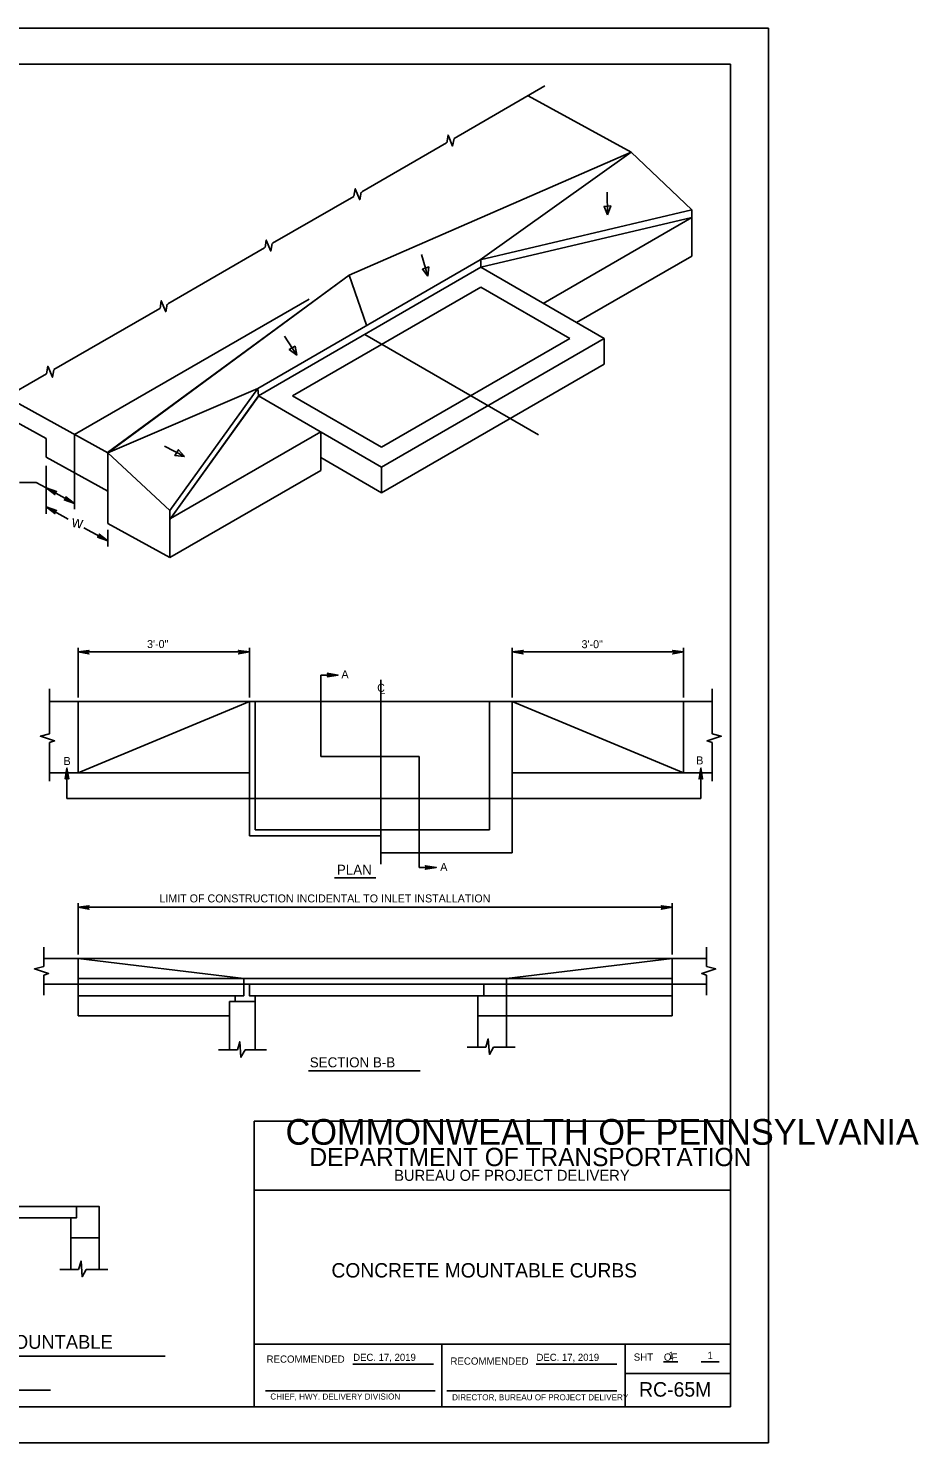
# Model space of a CAD drawing. Extents: x 638443 to 639347, y 298415 to 299009.
# Drawn here: x 638973 to 639347, y 298415 to 299009 of the extents above; entities that cross this region are included whole.
import ezdxf

# ---------------------------------------------------------------- set-up
doc = ezdxf.new("R2010")
doc.units = 0
for name, color, linetype in [('1', 7, 'Continuous'), ('2', 7, 'Continuous'), ('3', 7, 'Continuous'), ('PLT-BNDY', 7, 'Continuous')]:
    doc.layers.add(name, color=color, linetype=linetype)

msp = doc.modelspace()

# ---------------------------------------------------------------- linework, layer by layer
at = {"layer": '1'}
for p, q in [((639268.08, 298993.73), (638482.08, 298993.73)), ((639268.08, 298429.73), (639268.08, 298993.73)), ((639216.38, 298939.93), (639216.47, 298930.45)), ((639138.4, 298913.68), (639141.04, 298904.58)), ((639115.26, 298884.06), (639108.01, 298905.02)), ((639115.26, 298884.06), (639108.01, 298905.02)), ((639080.79, 298879.39), (639086.04, 298871.51)), ((639030.34, 298833.22), (639038.74, 298828.85)), ((639268.08, 298549.73), (639068.08, 298549.73)), ((639068.08, 298549.73), (639068.08, 298429.73)), ((639268.08, 298520.76), (639268.08, 298549.73)), ((639068.08, 298456.09), (639068.08, 298520.76)), ((639068.08, 298520.76), (639268.08, 298520.76)), ((639268.08, 298456.09), (639068.08, 298456.09)), ((639146.88, 298429.73), (639146.88, 298456.09)), ((639146.88, 298456.09), (639146.88, 298429.73)), ((639223.88, 298429.73), (639223.88, 298456.09)), ((639223.88, 298456.09), (639223.88, 298443.77)), ((639268.08, 298429.73), (639268.08, 298456.09)), ((639109.55, 298447.72), (639143.43, 298447.72)), ((639186.54, 298447.72), (639220.41, 298447.72)), ((639223.88, 298443.77), (639268.08, 298443.77)), ((639239.95, 298448.7), (639246.09, 298448.7)), ((639255.76, 298448.7), (639263.4, 298448.7)), ((639072.84, 298436.49), (639144.09, 298436.49)), ((639149.01, 298436.49), (639220.35, 298436.49)), ((638482.08, 298429.73), (639268.08, 298429.73)), ((639068.08, 298429.73), (639146.88, 298429.73)), ((639146.88, 298429.73), (639223.88, 298429.73))]:
    msp.add_line(p, q, dxfattribs=at)
for points in [[(639149, 298960.68), (639149.51, 298963.89), (639151.42, 298959.24), (639152.03, 298962.43)], [(639109.99, 298938.16), (639110.5, 298941.37), (639112.41, 298936.72), (639113.02, 298939.91)], [(639072.64, 298916.6), (639073.15, 298919.8), (639075.06, 298915.15), (639075.67, 298918.35)], [(639028.51, 298891.12), (639029.02, 298894.32), (639030.94, 298889.68), (639031.54, 298892.87)], [(638980.87, 298863.61), (638981.38, 298866.81), (638983.29, 298862.17), (638983.89, 298865.36)]]:
    msp.add_lwpolyline(points, dxfattribs=at)
for points in [[(639006.62, 298830.49), (639108.01, 298905.02), (639226.35, 298956.64), (639163, 298911.47), (639069.55, 298857.52)], [(639226.35, 298956.64), (639251.9, 298932.45), (639163, 298911.47)], [(639032.63, 298802.4), (639032.63, 298806.16), (639069.55, 298857.52), (639163, 298911.47), (639251.9, 298932.45), (639251.9, 298929.25), (639163.27, 298908.34), (639069.82, 298854.38)], [(639216.47, 298930.45), (639217.85, 298934.18), (639215.02, 298933.94)], [(639141.04, 298904.58), (639141.36, 298908.54), (639138.71, 298907.55)], [(639086.04, 298871.51), (639082.81, 298873.81), (639085.28, 298875.2)], [(639006.65, 298830.46), (639069.55, 298857.52), (639032.63, 298806.16)], [(639038.74, 298828.85), (639034.8, 298829.31), (639036.29, 298831.72)]]:
    msp.add_lwpolyline(points, close=True, dxfattribs=at)
at = {"layer": '2'}
for p, q in [((639190.22, 298984.5), (639152.07, 298962.47)), ((639183.15, 298980.42), (639226.35, 298956.65)), ((639148.86, 298960.62), (639113.28, 298940.08)), ((639226.35, 298956.64), (639108.01, 298905.02)), ((639163, 298911.47), (639226.35, 298956.64)), ((639251.9, 298932.45), (639226.35, 298956.64)), ((639109.92, 298938.14), (639075.78, 298918.43)), ((639251.9, 298932.45), (639163, 298911.47)), ((639251.9, 298929.25), (639251.9, 298932.45)), ((639251.9, 298929.25), (639163.27, 298908.34)), ((639189.48, 298893.21), (639251.9, 298929.25)), ((639251.9, 298913.08), (639251.9, 298929.25)), ((639072.46, 298916.51), (639031.76, 298893.01)), ((639203.48, 298885.12), (639251.9, 298913.08)), ((639163, 298911.47), (639069.55, 298857.52)), ((639163.27, 298908.34), (639069.82, 298854.38)), ((639163.27, 298908.34), (639163.27, 298911.55)), ((639215.06, 298878.44), (639163.27, 298908.34)), ((639108.01, 298905.02), (639006.52, 298830.58)), ((639091.17, 298895.04), (638992.65, 298838.16)), ((639163.27, 298900.03), (639084.22, 298854.38)), ((639200.66, 298878.44), (639163.27, 298900.03)), ((639028.46, 298891.11), (638983.92, 298865.39)), ((639187.47, 298838.05), (639114.5, 298880.18)), ((639121.6, 298832.8), (639200.66, 298878.44)), ((639121.6, 298824.48), (639215.06, 298878.44)), ((639215.06, 298867.65), (639215.06, 298878.44)), ((639121.6, 298813.69), (639215.06, 298867.65)), ((638980.79, 298863.58), (638959.89, 298851.51)), ((638964.03, 298853.9), (639006.65, 298830.46)), ((639069.55, 298857.52), (639006.62, 298830.49)), ((639032.63, 298806.16), (639069.55, 298857.52)), ((639032.63, 298802.4), (639069.95, 298854.31)), ((639069.82, 298854.38), (639069.64, 298857.5)), ((639121.6, 298824.48), (639069.82, 298854.38)), ((639121.6, 298832.8), (639084.22, 298854.38)), ((638964.1, 298845.54), (638980.67, 298836.43)), ((638980.67, 298836.43), (638980.67, 298828.6)), ((638992.65, 298806.78), (638992.65, 298838.16)), ((639032.94, 298802.84), (639096.02, 298839.25)), ((639096.02, 298823.08), (639096.02, 298839.25)), ((639006.65, 298830.46), (639006.65, 298800.77)), ((639032.63, 298806.16), (639006.65, 298830.46)), ((638980.67, 298828.6), (639006.65, 298814.31)), ((638980.67, 298804.82), (638980.67, 298824.94)), ((639121.6, 298813.69), (639096.02, 298828.46)), ((639121.6, 298813.69), (639121.6, 298824.48)), ((638976.45, 298818.03), (638969.52, 298818.03)), ((638976.45, 298818.03), (638980.67, 298815.71)), ((639032.63, 298786.48), (639096.02, 298823.08)), ((638980.67, 298815.71), (638992.65, 298809.12)), ((638980.67, 298807.75), (638989.99, 298802.62)), ((639032.63, 298802.4), (639032.63, 298806.16)), ((639006.65, 298800.77), (639032.62, 298786.48)), ((639032.63, 298786.48), (639032.63, 298802.4)), ((638996.56, 298799), (639006.65, 298793.46)), ((639006.65, 298791.12), (639006.65, 298798.16)), ((638994.07, 298727.74), (638994.07, 298748.53)), ((639039.51, 298746.85), (638994.07, 298746.85)), ((639066.07, 298746.85), (639039.51, 298746.85)), ((639066.07, 298727.74), (639066.07, 298748.53)), ((639176.47, 298727.74), (639176.47, 298748.53)), ((639221.91, 298746.85), (639176.47, 298746.85)), ((639248.47, 298746.85), (639221.91, 298746.85)), ((639248.47, 298727.74), (639248.47, 298748.53)), ((639096.13, 298737.1), (639096.13, 298702.94)), ((639096.13, 298737.1), (639103.33, 298737.1)), ((639121.27, 298657.7), (639121.27, 298735.08)), ((638982.07, 298731.29), (638982.07, 298712.37)), ((639260.47, 298731.29), (639260.47, 298712.37)), ((638994.07, 298726.06), (638982.07, 298726.06)), ((638994.07, 298696.06), (639066.07, 298726.06)), ((639066.07, 298726.06), (639176.47, 298726.06)), ((639066.07, 298726.06), (639066.07, 298669.66)), ((639068.47, 298726.06), (639068.47, 298672.06)), ((639166.87, 298726.06), (639166.87, 298672.06)), ((639248.47, 298696.06), (639176.47, 298726.06)), ((639176.47, 298726.06), (639176.47, 298662.46)), ((639248.47, 298726.06), (639260.47, 298726.06)), ((638982.07, 298708.82), (638982.07, 298692.59)), ((639260.47, 298708.82), (639260.47, 298692.59)), ((639096.13, 298702.94), (639137.36, 298702.94)), ((639137.36, 298702.94), (639137.36, 298656.32)), ((638994.07, 298696.06), (638982.07, 298696.06)), ((638989.41, 298685.26), (638989.41, 298698.04)), ((639248.47, 298696.06), (639260.47, 298696.06)), ((639255.71, 298685.26), (639255.71, 298698.04)), ((638989.41, 298685.26), (639255.71, 298685.26)), ((639066.07, 298669.66), (639121.27, 298669.66)), ((639068.47, 298672.06), (639121.27, 298672.06)), ((639166.87, 298672.06), (639121.27, 298672.06)), ((639176.47, 298662.46), (639121.27, 298662.46)), ((639137.36, 298656.32), (639144.56, 298656.32)), ((638994.07, 298619.74), (638994.07, 298641.31)), ((639129.98, 298639.63), (638994.07, 298639.63)), ((639243.67, 298639.63), (639129.98, 298639.63)), ((639243.67, 298619.74), (639243.67, 298641.31)), ((638979.67, 298622.79), (638979.67, 298614.67)), ((639258.07, 298622.79), (639258.07, 298614.67)), ((638979.67, 298618.06), (639258.07, 298618.06)), ((638981.35, 298618.06), (639089.1, 298618.06)), ((638994.07, 298594.06), (638994.07, 298618.06)), ((638994.07, 298618.06), (639063.67, 298609.66)), ((639243.67, 298618.06), (639174.07, 298609.66)), ((639243.67, 298594.06), (639243.67, 298618.06)), ((638979.67, 298611.13), (638979.67, 298602.63)), ((639258.07, 298611.13), (639258.07, 298602.63)), ((639063.67, 298607.26), (638979.67, 298607.26)), ((639063.67, 298609.66), (638994.07, 298609.66)), ((639063.67, 298609.66), (639063.67, 298607.26)), ((639174.07, 298609.66), (639063.67, 298609.66)), ((639066.07, 298607.26), (639063.67, 298607.26)), ((639063.67, 298607.26), (639063.67, 298602.46)), ((639174.07, 298609.66), (639243.67, 298609.66)), ((639174.07, 298609.66), (639174.07, 298607.26)), ((639174.07, 298607.26), (639258.07, 298607.26)), ((639060.07, 298602.46), (638994.07, 298602.46)), ((639057.67, 298600.06), (639068.47, 298600.06)), ((639057.67, 298600.06), (639057.67, 298579.66)), ((639063.67, 298602.46), (639060.07, 298602.46)), ((639060.07, 298602.46), (639060.07, 298600.06)), ((639067.75, 298602.46), (639089.1, 298602.46)), ((639068.47, 298600.06), (639068.47, 298602.46)), ((639068.47, 298602.46), (639068.47, 298579.66)), ((639164.47, 298602.46), (639243.67, 298602.46)), ((639057.67, 298594.06), (638994.07, 298594.06)), ((639174.07, 298594.06), (639243.67, 298594.06)), ((639057.67, 298579.66), (639057.67, 298579.79))]:
    msp.add_line(p, q, dxfattribs=at)
for points in [[(638984.76, 298814.09), (638984.46, 298813.9), (638980.67, 298815.71), (638984.76, 298814.09), (638985.04, 298814.15), (638980.67, 298815.71), (638984.25, 298813.51), (638984.23, 298813.16), (638980.67, 298815.71), (638984.34, 298812.87), (638984.23, 298813.16)], [(638988.58, 298810.75), (638988.87, 298810.95), (638992.65, 298809.12), (638988.58, 298810.75), (638988.29, 298810.69), (638992.65, 298809.12), (638989.09, 298811.33), (638989.11, 298811.68), (638992.65, 298809.12), (638989, 298811.98), (638989.11, 298811.68)], [(638984.76, 298806.13), (638984.46, 298805.93), (638980.67, 298807.75), (638984.76, 298806.13), (638985.04, 298806.19), (638980.67, 298807.75), (638984.25, 298805.55), (638984.23, 298805.2), (638980.67, 298807.75), (638984.34, 298804.9), (638984.23, 298805.2)], [(639002.57, 298795.09), (639002.86, 298795.29), (639006.65, 298793.46), (639002.57, 298795.09), (639002.28, 298795.03), (639006.65, 298793.46), (639003.08, 298795.67), (639003.1, 298796.02), (639006.65, 298793.46), (639002.99, 298796.32), (639003.1, 298796.02)], [(638998.41, 298746.19), (638998.26, 298746.51), (638994.07, 298746.85), (638998.41, 298746.19), (638998.63, 298746), (638994.07, 298746.85), (638998.27, 298746.95), (638998.43, 298747.26), (638994.07, 298746.85), (638998.67, 298747.46), (638998.43, 298747.26)], [(639061.72, 298746.19), (639061.88, 298746.51), (639066.07, 298746.85), (639061.72, 298746.19), (639061.51, 298746), (639066.07, 298746.85), (639061.87, 298746.95), (639061.71, 298747.26), (639066.07, 298746.85), (639061.47, 298747.46), (639061.71, 298747.26)], [(639180.81, 298746.19), (639180.66, 298746.51), (639176.47, 298746.85), (639180.81, 298746.19), (639181.03, 298746), (639176.47, 298746.85), (639180.67, 298746.95), (639180.83, 298747.26), (639176.47, 298746.85), (639181.07, 298747.46), (639180.83, 298747.26)], [(639244.12, 298746.19), (639244.28, 298746.51), (639248.47, 298746.85), (639244.12, 298746.19), (639243.91, 298746), (639248.47, 298746.85), (639244.27, 298746.95), (639244.11, 298747.26), (639248.47, 298746.85), (639243.87, 298747.46), (639244.11, 298747.26)], [(639098.97, 298737.65), (639099.14, 298737.33), (639103.33, 298737.1), (639098.97, 298737.65), (639098.75, 298737.84), (639103.33, 298737.1), (639099.14, 298736.9), (639098.99, 298736.58), (639103.33, 298737.1), (639098.75, 298736.38), (639098.99, 298736.58)], [(638982.07, 298712.37), (638978.3, 298711.42), (638984.2, 298709.46), (638982.07, 298708.82)], [(639260.47, 298712.37), (639264.24, 298711.42), (639258.34, 298709.46), (639260.47, 298708.82)], [(638988.87, 298693.69), (638989.18, 298693.85), (638989.41, 298698.04), (638988.87, 298693.69), (638988.68, 298693.46), (638989.41, 298698.04), (638989.62, 298693.85), (638989.93, 298693.7), (638989.41, 298698.04), (638990.14, 298693.46), (638989.93, 298693.7)], [(639255.16, 298693.69), (639255.48, 298693.85), (639255.71, 298698.04), (639255.16, 298693.69), (639254.97, 298693.46), (639255.71, 298698.04), (639255.91, 298693.85), (639256.23, 298693.7), (639255.71, 298698.04), (639256.44, 298693.46), (639256.23, 298693.7)], [(639140.2, 298656.86), (639140.36, 298656.55), (639144.56, 298656.32), (639140.2, 298656.86), (639139.98, 298657.06), (639144.56, 298656.32), (639140.37, 298656.11), (639140.21, 298655.8), (639144.56, 298656.32), (639139.98, 298655.59), (639140.21, 298655.8)], [(638998.41, 298638.97), (638998.26, 298639.29), (638994.07, 298639.63), (638998.41, 298638.97), (638998.63, 298638.77), (638994.07, 298639.63), (638998.27, 298639.73), (638998.43, 298640.04), (638994.07, 298639.63), (638998.67, 298640.24), (638998.43, 298640.04)], [(639239.32, 298638.97), (639239.48, 298639.29), (639243.67, 298639.63), (639239.32, 298638.97), (639239.11, 298638.77), (639243.67, 298639.63), (639239.47, 298639.73), (639239.31, 298640.04), (639243.67, 298639.63), (639239.07, 298640.24), (639239.31, 298640.04)], [(638979.67, 298614.67), (638975.77, 298613.7), (638981.67, 298611.73), (638979.67, 298611.13)], [(639258.07, 298614.67), (639261.97, 298613.7), (639256.07, 298611.73), (639258.07, 298611.13)], [(639066.07, 298602.46), (639164.47, 298602.46), (639164.47, 298607.26), (639066.07, 298607.26)], [(639066.07, 298607.26), (639066.07, 298602.46), (639077.57, 298602.46)], [(639077.57, 298607.26), (639066.07, 298607.26)], [(639164.47, 298607.26), (639174.07, 298607.26), (639174.07, 298594.06), (639162.07, 298594.06), (639162.07, 298602.46)], [(639162.07, 298594.06), (639162.07, 298580.86)], [(639174.07, 298580.86), (639174.07, 298594.06)], [(639061.03, 298579.66), (639062.02, 298583.14), (639062.48, 298576.58), (639064.25, 298579.66)], [(639157.53, 298580.86), (639165.43, 298580.86)], [(639165.43, 298580.86), (639166.42, 298584.34), (639166.89, 298577.78), (639168.65, 298580.86)], [(639168.65, 298580.86), (639177.65, 298580.86)], [(639053.13, 298579.66), (639061.03, 298579.66)], [(639064.25, 298579.66), (639073.25, 298579.66)], [(638993.38, 298513.92), (639002.98, 298513.92), (639002.98, 298500.72), (638990.98, 298500.72), (638990.98, 298509.12)], [(638990.98, 298500.72), (638990.98, 298487.52)], [(639002.98, 298487.52), (639002.98, 298500.72)], [(638994.34, 298487.52), (638995.33, 298490.99), (638995.8, 298484.44), (638997.56, 298487.52)], [(638986.44, 298487.52), (638994.34, 298487.52)], [(638997.56, 298487.52), (639006.56, 298487.52)]]:
    msp.add_lwpolyline(points, dxfattribs=at)
for points in [[(638994.07, 298696.06), (638994.07, 298726.06), (639066.07, 298726.06), (639066.07, 298696.06)], [(639248.47, 298696.06), (639248.47, 298726.06), (639176.47, 298726.06), (639176.47, 298696.06)], [(638940.58, 298513.92), (638940.58, 298509.12), (638993.38, 298509.12), (638993.38, 298513.92)]]:
    msp.add_lwpolyline(points, close=True, dxfattribs=at)
at = {"layer": '3'}
for p, q in [((639101.86, 298651.92), (639119.18, 298651.92)), ((639090.82, 298570.87), (639137.75, 298570.87)), ((638848.33, 298451.1), (639030.74, 298451.1)), ((638896.68, 298436.84), (638982.5, 298436.84))]:
    msp.add_line(p, q, dxfattribs=at)
at = {"layer": 'PLT-BNDY'}
msp.add_lwpolyline([(638443.08, 299008.73), (639284.08, 299008.73), (639284.08, 298414.73), (638443.08, 298414.73)], close=True, dxfattribs=at)

# ---------------------------------------------------------------- texts
at = {"layer": '1'}
msp.add_text('w', height=4.77, rotation=349.64525, dxfattribs=at).set_placement((638991.18, 298799.41))
for s, height, p in [('COMMONWEALTH OF PENNSYLVANIA', 10.7834, (639081.23, 298539.87)), ('DEPARTMENT OF TRANSPORTATION', 7.6843, (639091.29, 298530.88)), ('BUREAU OF PROJECT DELIVERY', 4.6221, (639126.87, 298524.71)), ('CONCRETE MOUNTABLE CURBS', 6.04, (639100.53, 298484.11)), ('RECOMMENDED', 3.048, (639073.24, 298448.32)), ('DEC. 17, 2019', 3, (639109.65, 298449.08)), ('RECOMMENDED', 3.048, (639150.49, 298447.49)), ('DEC. 17, 2019', 3, (639186.65, 298449.08)), ('SHT    OF', 3.048, (639227.49, 298449.16)), ('1', 3.05, (639242.11, 298449.89)), ('1', 3.05, (639258.47, 298449.89)), ('APPROVED', 0.0192, (639111.1, 298447.66)), ('RC-65M', 6.096, (639229.73, 298434.07)), ('CHIEF, HWY. DELIVERY DIVISION', 2.54, (639074.86, 298432.85)), ('DIRECTOR, BUREAU OF PROJECT DELIVERY', 2.54, (639151.21, 298432.54))]:
    msp.add_text(s, height=height, dxfattribs=at).set_placement(p)
at = {"layer": '3'}
for s, height, p in [('3\'-0"', 3.36, (639023.07, 298748.45)), ('3\'-0"', 3.36, (639205.58, 298748.39)), ('A', 3.36, (639104.72, 298735.77)), ('C', 3.36, (639119.74, 298730.06)), ('L', 3.36, (639120.66, 298729.26)), ('B', 3.36, (638987.98, 298699.34)), ('B', 3.36, (639253.76, 298699.58)), ('PLAN', 4.2, (639102.81, 298653.27)), ('A', 3.36, (639146.23, 298654.89)), ('LIMIT OF CONSTRUCTION INCIDENTAL TO INLET INSTALLATION', 3.36, (639028.24, 298641.63)), ('SECTION B-B', 4.2, (639091.42, 298572.37)), ('TREATMENT FOR CONCRETE MOUNTABLE', 5.76, (638847.75, 298454.18))]:
    msp.add_text(s, height=height, dxfattribs=at).set_placement(p)

doc.saveas('drawing.dxf')
